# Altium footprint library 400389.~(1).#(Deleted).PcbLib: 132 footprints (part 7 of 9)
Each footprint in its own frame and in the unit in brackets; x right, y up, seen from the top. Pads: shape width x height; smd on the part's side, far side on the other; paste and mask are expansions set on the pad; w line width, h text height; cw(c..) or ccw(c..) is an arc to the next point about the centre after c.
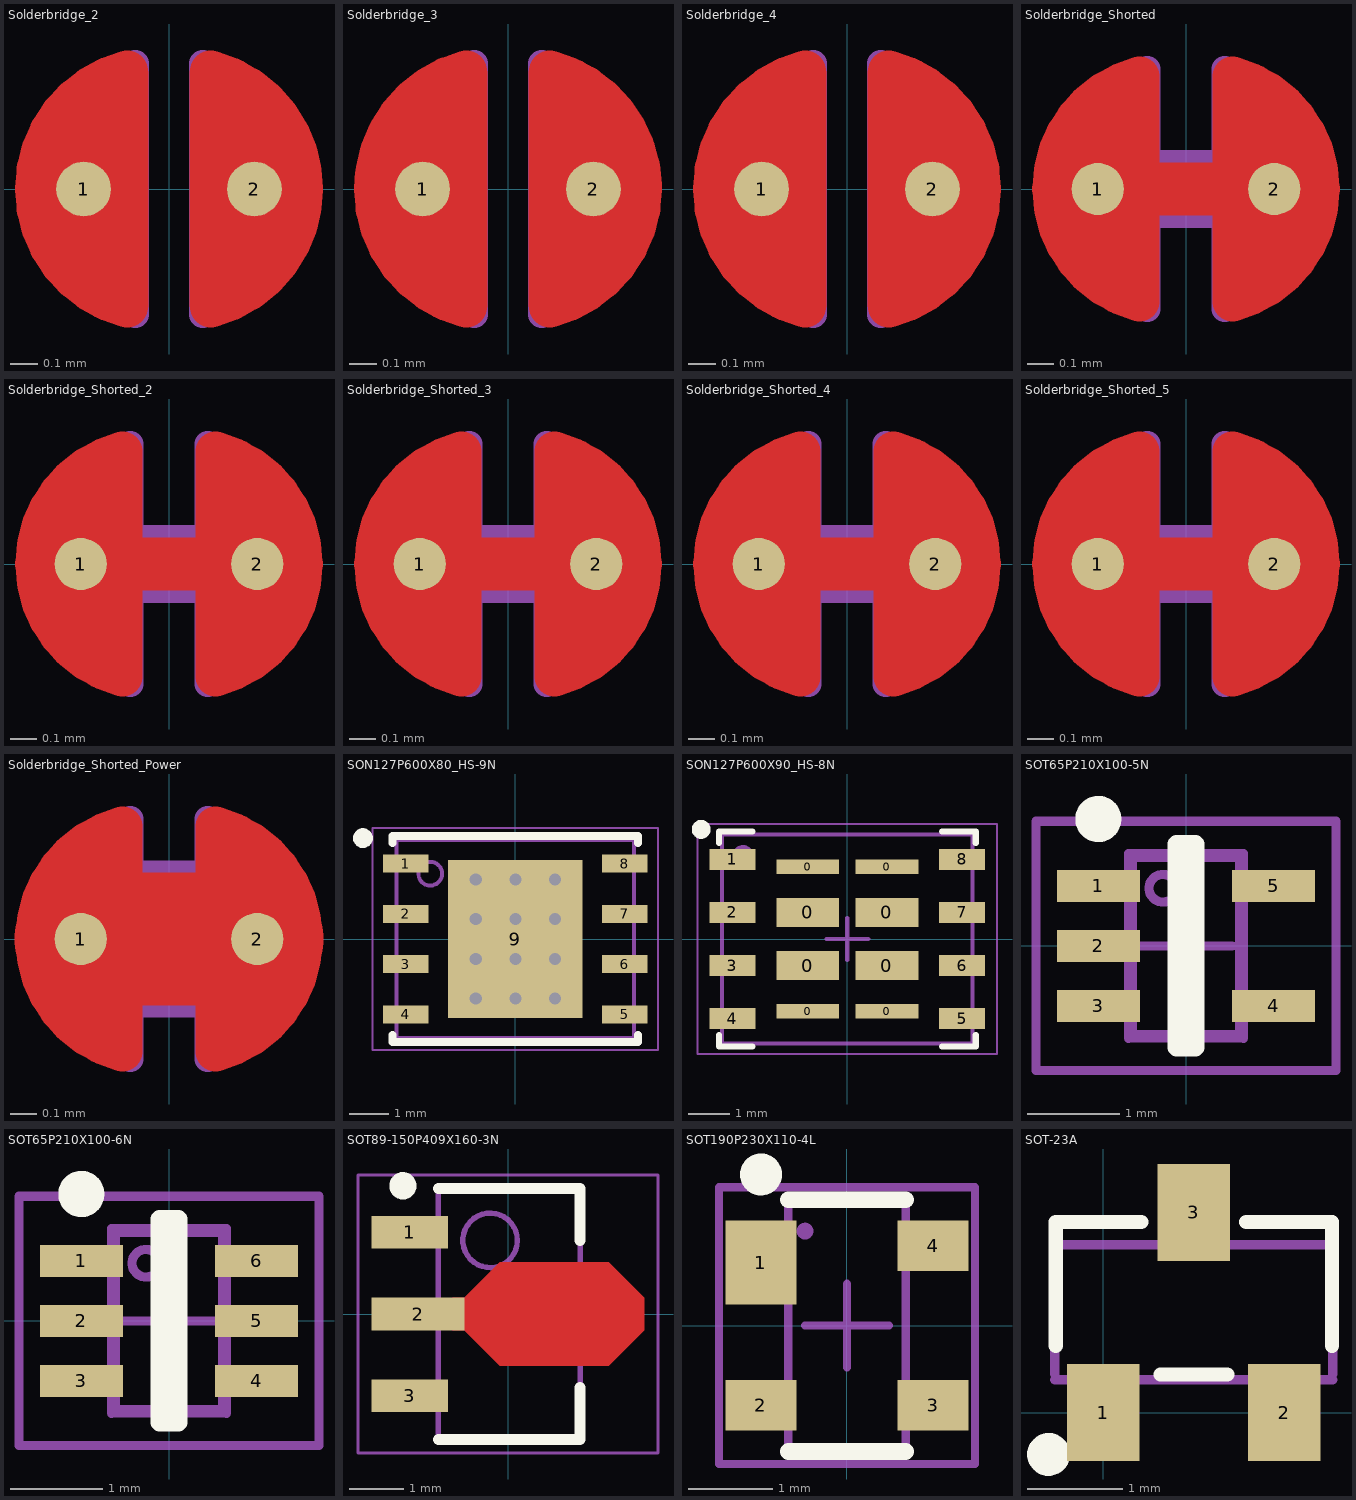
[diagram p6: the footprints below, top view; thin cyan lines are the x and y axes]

## Solderbridge_2 [mm]
pads (2):
  round 0.2 smd paste-10: 1(-0.312,0) 2(0.312,0)
Top Layer:
  region: -0.077,-0.432 -0.152,-0.505 -0.271,-0.467 -0.335,-0.424 -0.409,-0.351 -0.462,-0.292 -0.521,-0.193 -0.549,-0.099 -0.544,0.122 -0.518,0.193 -0.434,0.33 -0.351,0.411 -0.259,0.469 -0.157,0.5 -0.107,0.483 -0.077,0.43
  region: 0.077,0.432 0.152,0.505 0.271,0.467 0.335,0.424 0.409,0.351 0.462,0.292 0.521,0.193 0.549,0.099 0.544,-0.122 0.518,-0.193 0.434,-0.33 0.351,-0.411 0.259,-0.469 0.157,-0.5 0.107,-0.483 0.077,-0.43
  lines w0.152: -0.153,-0.431 cw(c-0.042,0) -0.487,0 cw(c-0.042,0) -0.153,0.431 ; 0.153,-0.431 ccw(c0.042,0) 0.441,-0.196 ccw(c0.042,0) 0.441,0.196 ccw(c0.042,0) 0.153,0.431
Top Solder:
  circle w0.61: c-0.003,0 r0.279
Mechanical 7:
  lines w0.1: -0.123,-0.459 cw(c-0.042,0) -0.123,0.459 -0.123,-0.459 ; 0.123,-0.459 ccw(c0.042,0) 0.123,0.459 0.123,-0.459
  text ".Designator" at -0.635,0.635 h0.38

## Solderbridge_3 [mm]
pads (2):
  round 0.2 smd paste-10: 1(-0.312,0) 2(0.312,0)
Top Layer:
  region: -0.077,-0.432 -0.152,-0.505 -0.271,-0.467 -0.335,-0.424 -0.409,-0.351 -0.462,-0.292 -0.521,-0.193 -0.549,-0.099 -0.544,0.122 -0.518,0.193 -0.434,0.33 -0.351,0.411 -0.259,0.469 -0.157,0.5 -0.107,0.483 -0.077,0.43
  region: 0.077,0.432 0.152,0.505 0.271,0.467 0.335,0.424 0.409,0.351 0.462,0.292 0.521,0.193 0.549,0.099 0.544,-0.122 0.518,-0.193 0.434,-0.33 0.351,-0.411 0.259,-0.469 0.157,-0.5 0.107,-0.483 0.077,-0.43
  lines w0.152: -0.153,-0.431 cw(c-0.042,0) -0.487,0 cw(c-0.042,0) -0.482,0.064 cw(c-0.042,0) -0.153,0.431 ; 0.153,-0.431 ccw(c0.042,0) 0.487,0 ccw(c0.042,0) 0.487,0.011 ccw(c0.042,0) 0.153,0.431
Top Solder:
  circle w0.61: c-0.003,0 r0.279
Mechanical 7:
  lines w0.1: -0.123,-0.459 cw(c-0.042,0) -0.123,0.459 -0.123,-0.459 ; 0.123,-0.459 ccw(c0.042,0) 0.123,0.459 0.123,-0.459
  text ".Designator" at -0.635,0.635 h0.38

## Solderbridge_4 [mm]
pads (2):
  round 0.2 smd paste-10: 1(-0.312,0) 2(0.312,0)
Top Layer:
  region: -0.077,-0.432 -0.152,-0.505 -0.271,-0.467 -0.335,-0.424 -0.409,-0.351 -0.462,-0.292 -0.521,-0.193 -0.549,-0.099 -0.544,0.122 -0.518,0.193 -0.434,0.33 -0.351,0.411 -0.259,0.469 -0.157,0.5 -0.107,0.483 -0.077,0.43
  region: 0.077,0.432 0.152,0.505 0.271,0.467 0.335,0.424 0.409,0.351 0.462,0.292 0.521,0.193 0.549,0.099 0.544,-0.122 0.518,-0.193 0.434,-0.33 0.351,-0.411 0.259,-0.469 0.157,-0.5 0.107,-0.483 0.077,-0.43
  lines w0.152: -0.153,-0.431 cw(c-0.042,0) -0.487,0 ; -0.153,0.431 ccw(c-0.042,0) -0.487,0 ; 0.153,-0.431 ccw(c0.042,0) 0.153,0.431 ; -0.487,0 ccw(c-0.042,0) -0.487,0
Top Solder:
  circle w0.61: c-0.003,0 r0.279
Mechanical 7:
  lines w0.1: -0.123,-0.459 cw(c-0.042,0) -0.123,0.459 -0.123,-0.459 ; 0.123,-0.459 ccw(c0.042,0) 0.123,0.459 0.123,-0.459
  text ".Designator" at -0.635,0.635 h0.38

## Solderbridge_Shorted [mm]
pads (2):
  round 0.2 smd paste-10: 1(-0.338,0) 2(0.338,0)
Top Layer:
  region: -0.102,-0.432 -0.178,-0.505 -0.296,-0.467 -0.361,-0.424 -0.434,-0.351 -0.488,-0.292 -0.546,-0.193 -0.574,-0.099 -0.569,0.122 -0.544,0.193 -0.46,0.33 -0.376,0.411 -0.284,0.469 -0.183,0.5 -0.132,0.483 -0.102,0.43
  region: 0.102,0.432 0.178,0.505 0.296,0.467 0.361,0.424 0.434,0.351 0.488,0.292 0.546,0.193 0.574,0.099 0.569,-0.122 0.544,-0.193 0.46,-0.33 0.376,-0.411 0.284,-0.469 0.183,-0.5 0.132,-0.483 0.102,-0.43
  lines w0.152: -0.178,-0.431 cw(c-0.068,0) -0.178,0.431 ; 0.178,-0.431 ccw(c0.068,0) 0.178,0.431
  lines w0.203: -0.338,0 0.338,0
Top Solder:
  circle w0.61: c0.028,0 r0.279
  circle w0.61: c-0.028,0 r0.279
Mechanical 7:
  lines w0.1: -0.148,-0.459 cw(c-0.067,0) -0.148,0.459 -0.148,0.1 0.148,0.1 0.148,0.459 cw(c0.067,0) 0.148,-0.459 0.148,-0.1 -0.148,-0.1 -0.148,-0.459
  text ".Designator" at -0.635,0.635 h0.38

## Solderbridge_Shorted_2 [mm]
pads (2):
  round 0.2 smd paste-10: 1(-0.338,0) 2(0.338,0)
Top Layer:
  region: -0.102,-0.432 -0.178,-0.505 -0.296,-0.467 -0.361,-0.424 -0.434,-0.351 -0.488,-0.292 -0.546,-0.193 -0.574,-0.099 -0.569,0.122 -0.544,0.193 -0.46,0.33 -0.376,0.411 -0.284,0.469 -0.183,0.5 -0.132,0.483 -0.102,0.43
  region: 0.102,0.432 0.178,0.505 0.296,0.467 0.361,0.424 0.434,0.351 0.488,0.292 0.546,0.193 0.574,0.099 0.569,-0.122 0.544,-0.193 0.46,-0.33 0.376,-0.411 0.284,-0.469 0.183,-0.5 0.132,-0.483 0.102,-0.43
  lines w0.152: -0.178,-0.431 cw(c-0.068,0) -0.178,0.431 ; 0.178,-0.431 ccw(c0.068,0) 0.178,0.431
  lines w0.203: -0.338,0 0.338,0
Top Solder:
  circle w0.61: c0.028,0 r0.279
  circle w0.61: c-0.028,0 r0.279
Mechanical 7:
  lines w0.1: -0.148,-0.459 cw(c-0.067,0) -0.148,0.459 -0.148,0.1 0.148,0.1 0.148,0.459 cw(c0.067,0) 0.148,-0.459 0.148,-0.1 -0.148,-0.1 -0.148,-0.459
  text ".Designator" at -0.635,0.635 h0.38

## Solderbridge_Shorted_3 [mm]
pads (2):
  round 0.2 smd paste-10: 1(-0.338,0) 2(0.338,0)
Top Layer:
  region: 0.102,0.432 0.178,0.505 0.296,0.467 0.361,0.424 0.434,0.351 0.488,0.292 0.546,0.193 0.574,0.099 0.569,-0.122 0.544,-0.193 0.46,-0.33 0.376,-0.411 0.284,-0.469 0.183,-0.5 0.132,-0.483 0.102,-0.43
  region: -0.102,-0.432 -0.178,-0.505 -0.296,-0.467 -0.361,-0.424 -0.434,-0.351 -0.488,-0.292 -0.546,-0.193 -0.574,-0.099 -0.569,0.122 -0.544,0.193 -0.46,0.33 -0.376,0.411 -0.284,0.469 -0.183,0.5 -0.132,0.483 -0.102,0.43
  lines w0.152: -0.178,-0.431 cw(c-0.068,0) -0.178,0.431 ; 0.178,-0.431 ccw(c0.068,0) 0.512,0 ccw(c0.068,0) 0.178,0.431
  lines w0.203: -0.338,0 0.338,0
Top Solder:
  circle w0.61: c-0.028,0 r0.279
  circle w0.61: c0.028,0 r0.279
Mechanical 7:
  lines w0.1: -0.148,-0.459 cw(c-0.067,0) -0.148,0.459 -0.148,0.1 0.148,0.1 0.148,0.459 cw(c0.067,0) 0.148,-0.459 0.148,-0.1 -0.148,-0.1 -0.148,-0.459
  text ".Designator" at -0.635,0.635 h0.38

## Solderbridge_Shorted_4 [mm]
pads (2):
  round 0.2 smd paste-10: 1(-0.338,0) 2(0.338,0)
Top Layer:
  region: 0.102,0.432 0.178,0.505 0.296,0.467 0.361,0.424 0.434,0.351 0.488,0.292 0.546,0.193 0.574,0.099 0.569,-0.122 0.544,-0.193 0.46,-0.33 0.376,-0.411 0.284,-0.469 0.183,-0.5 0.132,-0.483 0.102,-0.43
  region: -0.102,-0.432 -0.178,-0.505 -0.296,-0.467 -0.361,-0.424 -0.434,-0.351 -0.488,-0.292 -0.546,-0.193 -0.574,-0.099 -0.569,0.122 -0.544,0.193 -0.46,0.33 -0.376,0.411 -0.284,0.469 -0.183,0.5 -0.132,0.483 -0.102,0.43
  lines w0.152: -0.178,-0.431 cw(c-0.068,0) -0.178,0.431 ; 0.178,-0.431 ccw(c0.068,0) 0.178,0.431
  lines w0.203: -0.338,0 0.338,0
Top Solder:
  circle w0.61: c-0.028,0 r0.279
  circle w0.61: c0.028,0 r0.279
Mechanical 7:
  lines w0.1: -0.148,-0.459 cw(c-0.067,0) -0.148,0.459 -0.148,0.1 0.148,0.1 0.148,0.459 cw(c0.067,0) 0.148,-0.459 0.148,-0.1 -0.148,-0.1 -0.148,-0.459
  text ".Designator" at -0.635,0.635 h0.38

## Solderbridge_Shorted_5 [mm]
pads (2):
  round 0.2 smd paste-10: 1(-0.338,0) 2(0.338,0)
Top Layer:
  region: -0.102,-0.432 -0.178,-0.505 -0.296,-0.467 -0.361,-0.424 -0.434,-0.351 -0.488,-0.292 -0.546,-0.193 -0.574,-0.099 -0.569,0.122 -0.544,0.193 -0.46,0.33 -0.376,0.411 -0.284,0.469 -0.183,0.5 -0.132,0.483 -0.102,0.43
  region: 0.102,0.432 0.178,0.505 0.296,0.467 0.361,0.424 0.434,0.351 0.488,0.292 0.546,0.193 0.574,0.099 0.569,-0.122 0.544,-0.193 0.46,-0.33 0.376,-0.411 0.284,-0.469 0.183,-0.5 0.132,-0.483 0.102,-0.43
  lines w0.152: -0.178,-0.431 cw(c-0.068,0) -0.178,0.431 ; 0.178,-0.431 ccw(c0.068,0) 0.178,0.431
  lines w0.203: -0.338,0 0.338,0
Top Solder:
  circle w0.61: c0.028,0 r0.279
  circle w0.61: c-0.028,0 r0.279
Mechanical 7:
  lines w0.1: -0.148,-0.459 cw(c-0.067,0) -0.148,0.459 -0.148,0.1 0.148,0.1 0.148,0.459 cw(c0.067,0) 0.148,-0.459 0.148,-0.1 -0.148,-0.1 -0.148,-0.459
  text ".Designator" at -0.635,0.635 h0.38

## Solderbridge_Shorted_Power [mm]
pads (2):
  round 0.2 smd paste-10: 1(-0.338,0) 2(0.338,0)
Top Layer:
  region: -0.102,-0.432 -0.178,-0.505 -0.296,-0.467 -0.361,-0.424 -0.434,-0.351 -0.488,-0.292 -0.546,-0.193 -0.574,-0.099 -0.569,0.122 -0.544,0.193 -0.46,0.33 -0.376,0.411 -0.284,0.469 -0.183,0.5 -0.132,0.483 -0.102,0.43
  region: 0.102,0.432 0.178,0.505 0.296,0.467 0.361,0.424 0.434,0.351 0.488,0.292 0.546,0.193 0.574,0.099 0.569,-0.122 0.544,-0.193 0.46,-0.33 0.376,-0.411 0.284,-0.469 0.183,-0.5 0.132,-0.483 0.102,-0.43
  lines w0.152: -0.178,-0.431 cw(c-0.068,0) -0.178,0.431 ; 0.178,-0.431 ccw(c0.068,0) 0.178,0.431
  lines w0.508: -0.338,0 0.338,0
Top Solder:
  circle w0.61: c0.028,0 r0.279
  circle w0.61: c-0.028,0 r0.279
Mechanical 7:
  lines w0.1: 0.148,-0.25 0.148,-0.459 ccw(c0.067,0) 0.148,0.459 0.148,0.25 -0.148,0.25 -0.148,0.459 ccw(c-0.067,0) -0.148,-0.459 -0.148,-0.25 0.175,-0.25
  text ".Designator" at -0.635,0.635 h0.38

## SON127P600X80_HS-9N [mm]
pads (9):
  rect 1.15x0.45 smd: 1(-2.77,1.905) 2(-2.77,0.635) 3(-2.77,-0.635) 4(-2.77,-1.905) 5(2.77,-1.905) 6(2.77,-0.635) 7(2.77,0.635) 8(2.77,1.905)
  rect 3.4x4 smd paste-1.7: 9(0,0)
via -1,1.5 diameter 0.61 hole 0.305
via 0,1.5 diameter 0.61 hole 0.305
via 1,1.5 diameter 0.61 hole 0.305
via -1,0.5 diameter 0.61 hole 0.305
via 0,0.5 diameter 0.61 hole 0.305
via 1,0.5 diameter 0.61 hole 0.305
via -1,-0.5 diameter 0.61 hole 0.305
via 0,-0.5 diameter 0.61 hole 0.305
via 1,-0.5 diameter 0.61 hole 0.305
via -1,-1.5 diameter 0.61 hole 0.305
via 0,-1.5 diameter 0.61 hole 0.305
via 1,-1.5 diameter 0.61 hole 0.305
Top Overlay:
  circle w0.25: c-3.85,2.55 r0.125
  lines w0.2: -3.1,-2.43 -3.1,-2.6 3.1,-2.6 3.1,-2.43 ; -3.1,2.43 -3.1,2.6 3.1,2.6 3.1,2.43
Top Paste:
  rectangle: -1.595,0.765 -0.665,1.895
  rectangle: -1.595,-0.565 -0.665,0.565
  rectangle: -1.595,-1.895 -0.665,-0.765
  rectangle: -0.465,0.765 0.465,1.895
  rectangle: -0.465,-0.565 0.465,0.565
  rectangle: -0.465,-1.895 0.465,-0.765
  rectangle: 0.665,0.765 1.595,1.895
  rectangle: 0.665,-0.565 1.595,0.565
  rectangle: 0.665,-1.895 1.595,-0.765
Mechanical 7:
  circle w0.1: c-2.15,1.65 r0.3
  lines w0.1: -3,-2.5 -3,2.5 3,2.5 3,-2.5 -3,-2.5
  text ".Designator" at -0.5,-0.175 h0.38
Mechanical 15:
  lines w0.05: -3.605,-2.8 -3.605,2.8 3.605,2.8 3.605,-2.8 -3.605,-2.8
  lines w0.1: -0.5,0 0.5,0 ; 0,-0.5 0,0.5
3D body "SON127P600X80_HS-9N.step": height 0.8, standoff 0, extent -3.051,-2.55 3.051,2.55

## SON127P600X90_HS-8N [mm]
pads (16):
  rect 1.5x0.35 smd paste-1.27: 0(-0.95,-1.73) 0(-0.95,1.73) 0(0.95,-1.73) 0(0.95,1.73)
  rect 1.5x0.7 smd paste-1.27: 0(-0.95,-0.635) 0(-0.95,0.635) 0(0.95,-0.635) 0(0.95,0.635)
  rect 1.1x0.5 smd paste-1.27: 1(-2.75,1.905) 2(-2.75,0.635) 3(-2.75,-0.635) 4(-2.75,-1.905) 5(2.75,-1.905) 6(2.75,-0.635) 7(2.75,0.635) 8(2.75,1.905)
Top Overlay:
  circle w0.25: c-3.5,2.625 r0.1
  lines w0.15: -3.075,-2.3 -3.075,-2.575 -2.27,-2.575 ; -3.075,2.3 -3.075,2.575 -2.27,2.575 ; 2.27,-2.575 3.075,-2.575 3.075,-2.3 ; 2.27,2.575 3.075,2.575 3.075,2.3
Mechanical 7:
  circle w0.1: c-2.5,2 r0.2
  lines w0.1: -3.001,-2.105 -3.111,-2.105 -3.111,-1.705 -3.001,-1.705 ; -3.001,-0.835 -3.111,-0.835 -3.111,-0.435 -3.001,-0.435 ; -3.001,0.435 -3.111,0.435 -3.111,0.835 -3.001,0.835 ; -3.001,1.705 -3.111,1.705 -3.111,2.105 -3.001,2.105 ; 3.001,-2.105 3.111,-2.105 3.111,-1.705 3.001,-1.705 ; 3.001,-0.835 3.111,-0.835 3.111,-0.435 3.001,-0.435 ; 3.001,0.435 3.111,0.435 3.111,0.835 3.001,0.835 ; 3.001,1.705 3.111,1.705 3.111,2.105 3.001,2.105 ; -3,-2.5 3,-2.5 3,2.5 -3,2.5 -3,-2.5
  text ".Designator" at -0.35,-0.15 h0.3
Mechanical 15:
  lines w0.05: -3.585,-2.75 3.585,-2.75 3.585,2.75 -3.585,2.75 -3.585,-2.75
  lines w0.1: -0.5,0 0.5,0 ; 0,-0.5 0,0.5

## SOT65P210X100-5N [mm]
pads (5):
  rect 0.9x0.35 smd: 1(-0.95,0.65) 2(-0.95,0) 3(-0.95,-0.65) 4(0.95,-0.65) 5(0.95,0.65)
Top Overlay:
  circle w0.25: c-0.95,1.375 r0.125
  lines w0.2: -0.1,-1.1 0.1,-1.1 0.1,1.1 -0.1,1.1 -0.1,-1.1
Mechanical 7:
  circle w0.1: c-0.25,0.625 r0.15
  lines w0.1: -1.048,-0.748 -1.048,-0.545 ; -1.048,-0.101 -1.048,0.103 ; -1.048,0.547 -1.048,0.75 ; -0.862,-0.76 -0.862,-0.532 ; -0.862,-0.113 -0.862,0.115 ; -0.862,0.534 -0.862,0.762 ; -0.624,-0.999 -0.624,-0.998 ; -0.624,-0.76 -0.624,-0.998 ; -0.624,-0.532 -0.624,-0.113 ; -0.624,0.115 -0.624,0.534 ; -0.624,0.762 -0.624,1 0.624,1 0.624,0.762 ; 0.624,-0.999 0.624,-0.998 ; 0.624,-0.76 0.624,-0.998 ; 0.624,-0.532 0.624,0.534 ; 0.862,-0.76 0.862,-0.532 ; 0.862,0.534 0.862,0.762 ; 1.048,-0.748 1.048,-0.545 ; 1.048,0.547 1.048,0.75 ; -0.624,-0.998 0.624,-0.998 ; -1.048,-0.76 -1.048,-0.532 -0.611,-0.532 -0.611,-0.76 -1.048,-0.76 ; -1.048,-0.113 -0.611,-0.113 -0.611,0.115 -1.048,0.115 -1.048,-0.113 ; -1.048,0.534 -1.048,0.762 -0.611,0.762 -0.611,0.534 -1.048,0.534 ; -0.582,-0.96 0.582,-0.96 0.582,0.961 -0.582,0.961 -0.582,-0.96 ; 0.611,-0.76 1.048,-0.76 1.048,-0.532 0.611,-0.532 0.611,-0.76 ; 0.611,0.534 1.048,0.534 1.048,0.762 0.611,0.762 0.611,0.534
  text ".Designator" at 0.4,-0.55 h0.38
Mechanical 15:
  lines w0.1: -0.5,0 0.5,0 ; 0,-0.5 0,0.5 ; -1.625,-1.35 -1.625,1.35 1.625,1.35 1.625,-1.35 -1.625,-1.35
3D body "User Library-SC70-5.STEP": height 0.97, standoff 0, extent -1.1,-1 1.1,1

## SOT65P210X100-6N [mm]
pads (6):
  rect 0.9x0.35 smd: 1(-0.95,0.65) 2(-0.95,0) 3(-0.95,-0.65) 4(0.95,-0.65) 5(0.95,0) 6(0.95,0.65)
Top Overlay:
  circle w0.25: c-0.95,1.375 r0.125
  lines w0.2: -0.1,-1.1 -0.1,1.1 0.1,1.1 0.1,-1.1 -0.1,-1.1
Mechanical 7:
  circle w0.1: c-0.25,0.625 r0.15
  lines w0.1: -1.048,-0.748 -1.048,-0.545 ; -1.048,-0.101 -1.048,0.103 ; -1.048,0.547 -1.048,0.75 ; -0.862,-0.76 -0.862,-0.532 ; -0.862,-0.113 -0.862,0.115 ; -0.862,0.534 -0.862,0.762 ; -0.624,-0.999 -0.624,-0.998 ; -0.624,-0.76 -0.624,-0.998 ; -0.624,-0.532 -0.624,-0.113 ; -0.624,0.115 -0.624,0.534 ; -0.624,0.762 -0.624,1 0.624,1 0.624,0.762 ; 0.624,-0.999 0.624,-0.998 ; 0.624,-0.76 0.624,-0.998 ; 0.624,-0.532 0.624,-0.113 ; 0.624,0.115 0.624,0.534 ; 0.862,-0.76 0.862,-0.532 ; 0.862,-0.113 0.862,0.115 ; 0.862,0.534 0.862,0.762 ; 1.048,-0.748 1.048,-0.545 ; 1.048,-0.101 1.048,0.103 ; 1.048,0.547 1.048,0.75 ; -0.624,-0.998 0.624,-0.998 ; -1.048,-0.76 -1.048,-0.532 -0.611,-0.532 -0.611,-0.76 -1.048,-0.76 ; -1.048,-0.113 -0.611,-0.113 -0.611,0.115 -1.048,0.115 -1.048,-0.113 ; -1.048,0.534 -1.048,0.762 -0.611,0.762 -0.611,0.534 -1.048,0.534 ; -0.582,-0.96 0.582,-0.96 0.582,0.961 -0.582,0.961 -0.582,-0.96 ; 0.611,-0.76 1.048,-0.76 1.048,-0.532 0.611,-0.532 0.611,-0.76 ; 0.611,-0.113 0.611,0.115 1.048,0.115 1.048,-0.113 0.611,-0.113 ; 0.611,0.534 1.048,0.534 1.048,0.762 0.611,0.762 0.611,0.534
  text ".Designator" at 0.4,-0.55 h0.38
Mechanical 15:
  lines w0.1: -0.5,0 0.5,0 ; 0,-0.5 0,0.5 ; -1.625,-1.35 1.625,-1.35 1.625,1.35 -1.625,1.35 -1.625,-1.35
3D body "SW3dPS-SC70-6.STEP": height 0.92, standoff -0.03, extent -1.05,-1 1.05,1

## SOT89-150P409X160-3N [mm]
pads (3):
  rect 1.4x0.6 smd: 1(-1.8,1.5) 3(-1.8,-1.5)
  rect 1.7x0.6 smd: 2(-1.65,0)
Top Layer:
  rectangle: -1.016,-0.301 -0.635,0.299
  region: -0.8,0.3 -0.15,0.95 1.85,0.95 2.5,0.3 2.5,-0.3 1.85,-0.95 -0.15,-0.95 -0.8,-0.3
Top Overlay:
  circle w0.25: c-1.928,2.35 r0.125
  lines w0.2: -1.278,-2.3 1.322,-2.3 1.322,-1.35 ; -1.278,2.3 1.322,2.3 1.322,1.35
Mechanical 7:
  circle w0.1: c-0.327,1.35 r0.5
  lines w0.1: -1.278,-2.3 -1.278,2.3 1.322,2.3 1.322,-2.3 -1.278,-2.3
  text ".Designator" at -0.889,-0.127 h0.38
Mechanical 15:
  lines w0.05: -2.75,-2.55 -2.75,2.55 2.75,2.55 2.75,-2.55 -2.75,-2.55
  lines w0.1: -0.478,0 0.522,0 ; 0.022,-0.5 0.022,0.5
3D body "SOT89-150P409X160-3N.step": height 1.6, standoff 0, extent -2.2,-2.297 1.93,2.297

## SOT190P230X110-4L [mm]
pads (4):
  rect 0.85x1 smd: 1(-1.025,0.75)
  rect 0.85x0.6 smd: 2(-1.025,-0.95) 3(1.025,-0.95) 4(1.025,0.95)
Top Overlay:
  circle w0.25: c-1.025,1.8 r0.125
  lines w0.2: -0.7,-1.5 0.7,-1.5 ; -0.7,1.5 0.7,1.5
Mechanical 7:
  circle w0.1: c-0.5,1.125 r0.05
  lines w0.1: -0.7,-1.5 -0.7,1.5 0.7,1.5 0.7,-1.5 -0.7,-1.5
  text ".Designator" at -0.225,1.375 h0.69
Mechanical 15:
  lines w0.1: -0.5,0 0.5,0 ; 0,-0.5 0,0.5 ; -1.525,-1.65 -1.525,1.65 1.525,1.65 1.525,-1.65 -1.525,-1.65
3D body "User Library-sot143.step": height 1, standoff 0, extent -1.21,-1.46 1.21,1.46

## SOT-23A [mil]
pads (3):
  rect 30x40 smd: 1(0,0) 2(74.8,0) 3(37.4,82.68)
Top Overlay:
  circle w9.84: c-22.6,-17.32 r3.94
  lines w5.91: -19.68,27.56 -19.68,78.74 15.75,78.74 ; 23.62,15.75 51.18,15.75 ; 59.06,78.74 94.49,78.74 94.49,27.56
Mechanical 7:
  lines w3.94: -20.07,13.56 94.89,13.56 ; -20.07,15.75 -20.07,69.32 94.89,69.32 94.89,15.75
  lines w4.02: -8.27,13.56 -8.27,-7.51 8.27,-7.51 8.27,13.56 ; 29.13,69.32 29.13,90.18 45.67,90.18 45.67,69.32 ; 66.54,13.56 66.54,-7.51 83.07,-7.51 83.07,13.56
  text ".Designator" at 16.48,34.51 h15
3D body "User Library-sot23-1.step": height 39.37, standoff 0, extent -20.07,-4.72 94.89,87.41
